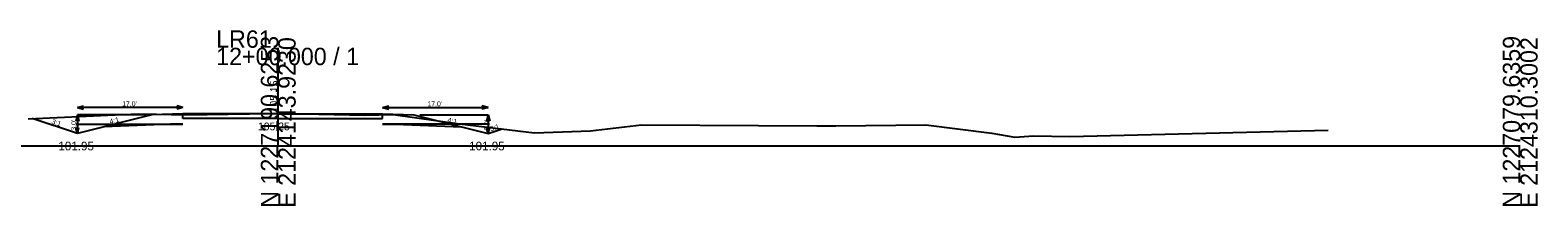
# Model space of a CAD drawing. Extents: x -26 to 1403, y -10 to 9574.
# Drawn here: x 1160 to 1402.8, y 1990.3 to 2018.6 of the extents above; entities that cross this region are included whole.
import ezdxf

# ---------------------------------------------------------------- set-up
doc = ezdxf.new("R2010")
doc.units = 0
for name, color, linetype in [('XS_CELL', 7, 'Continuous'), ('XS_P_FINISHED_GRADE', 7, 'Continuous'), ('XS_P_FINISHED_GRADE_ELEV_TX', 7, 'Continuous'), ('XS_P_SUBGRADE_GRANULAR', 7, 'Continuous'), ('XS_P_SUBGRADE_PAVEMENT', 7, 'Continuous'), ('XS_P_TX_CLEARZONE', 7, 'Continuous'), ('XS_P_TX_DCH', 7, 'Continuous'), ('XS_P_TX_FS_BS', 7, 'Continuous'), ('XS_X_GROUND', 7, 'Continuous'), ('XS_X_GROUND_TX', 7, 'Continuous')]:
    doc.layers.add(name, color=color, linetype=linetype)

msp = doc.modelspace()

# ---------------------------------------------------------------- linework, layer by layer
at = {"layer": 'XS_CELL'}
for p, q in [((1200, 2000), (1200, 2015.78)), ((1000, 2000), (1200, 2000)), ((1200, 2000), (1400, 2000))]:
    msp.add_line(p, q, dxfattribs=at)
at = {"layer": 'XS_P_FINISHED_GRADE'}
for p, q in [((1167.66, 2001.95), (1160.37, 2004.38)), ((1179.66, 2004.95), (1167.66, 2001.95)), ((1184.66, 2005.15), (1179.66, 2004.95)), ((1200, 2005.15), (1184.66, 2005.15)), ((1200, 2005.15), (1216.81, 2005.15)), ((1216.81, 2005.15), (1221.81, 2004.95)), ((1221.81, 2004.95), (1233.81, 2001.95)), ((1233.81, 2001.95), (1236.04, 2002.7))]:
    msp.add_line(p, q, dxfattribs=at)
at = {"layer": 'XS_P_SUBGRADE_GRANULAR'}
for p, q in [((1167.46, 2003.45), (1184.66, 2003.45)), ((1182.66, 2003.45), (1171.94, 2003.03)), ((1184.66, 2003.45), (1182.66, 2003.45)), ((1234.01, 2003.45), (1216.81, 2003.45)), ((1216.81, 2003.45), (1218.81, 2003.45)), ((1218.81, 2003.45), (1229.53, 2003.03))]:
    msp.add_line(p, q, dxfattribs=at)
at = {"layer": 'XS_P_SUBGRADE_PAVEMENT'}
for p, q in [((1184.66, 2004.4), (1184.66, 2005.15)), ((1200, 2004.4), (1184.66, 2004.4)), ((1200, 2004.4), (1216.81, 2004.4)), ((1216.81, 2004.4), (1216.81, 2005.15))]:
    msp.add_line(p, q, dxfattribs=at)
at = {"layer": 'XS_P_TX_CLEARZONE'}
for p, q in [((1167.66, 2006.15), (1168.66, 2006.4)), ((1167.66, 2006.15), (1168.66, 2005.9)), ((1184.66, 2006.15), (1167.66, 2006.15)), ((1184.66, 2006.15), (1183.66, 2006.4)), ((1184.66, 2006.15), (1183.66, 2005.9)), ((1216.81, 2006.15), (1217.81, 2006.4)), ((1216.81, 2006.15), (1217.81, 2005.9)), ((1216.81, 2006.15), (1233.81, 2006.15)), ((1233.81, 2006.15), (1232.81, 2006.4)), ((1233.81, 2006.15), (1232.81, 2005.9)), ((1167.66, 2004.95), (1167.41, 2003.95)), ((1167.66, 2004.95), (1167.91, 2003.95)), ((1167.66, 2004.95), (1167.66, 2001.95)), ((1178.66, 2004.95), (1167.66, 2004.95)), ((1222.81, 2004.95), (1233.81, 2004.95)), ((1233.81, 2004.95), (1233.56, 2003.95)), ((1233.81, 2004.95), (1233.81, 2001.95)), ((1233.81, 2004.95), (1234.06, 2003.95)), ((1167.66, 2001.95), (1167.41, 2002.95)), ((1167.66, 2001.95), (1167.91, 2002.95)), ((1233.81, 2001.95), (1233.56, 2002.95)), ((1233.81, 2001.95), (1234.06, 2002.95))]:
    msp.add_line(p, q, dxfattribs=at)
at = {"layer": 'XS_X_GROUND'}
for p, q in [((1159.72, 2004.35), (1173.76, 2004.95)), ((1173.76, 2004.95), (1177.52, 2005.12)), ((1177.52, 2005.12), (1180.37, 2005.06)), ((1180.37, 2005.06), (1185.14, 2004.96)), ((1185.14, 2004.96), (1195.37, 2005.16)), ((1195.37, 2005.16), (1199.82, 2005.26)), ((1199.82, 2005.26), (1206.54, 2005.1)), ((1206.54, 2005.1), (1213.95, 2004.91)), ((1213.95, 2004.91), (1218.51, 2005.01)), ((1218.51, 2005.01), (1229.2, 2003.51)), ((1229.2, 2003.51), (1241.29, 2002.08)), ((1250.26, 2002.41), (1258.51, 2003.36)), ((1258.51, 2003.36), (1286.75, 2003.19)), ((1286.75, 2003.19), (1288.25, 2003.21)), ((1288.25, 2003.21), (1289.8, 2003.18)), ((1289.8, 2003.18), (1304.27, 2003.37)), ((1304.27, 2003.37), (1314.92, 2002.02)), ((1241.29, 2002.08), (1250.26, 2002.41)), ((1314.92, 2002.02), (1318.64, 2001.37)), ((1318.64, 2001.37), (1321.61, 2001.6)), ((1321.61, 2001.6), (1327.48, 2001.5)), ((1327.48, 2001.5), (1369.05, 2002.5))]:
    msp.add_line(p, q, dxfattribs=at)

# ---------------------------------------------------------------- texts
at = {"layer": 'XS_CELL'}
for s, p in [('LR61', (1190, 2015.78)), ('12+00.000 / 1', (1190, 2012.98))]:
    msp.add_text(s, height=2.8, dxfattribs=at).set_placement(p)
for s, p in [('N 1227190.6253', (1200, 1990)), ('E 2124143.9230', (1202.8, 1990)), ('N 1227079.6359', (1400, 1990)), ('E 2124310.3002', (1402.8, 1990))]:
    msp.add_text(s, height=2.8, rotation=90, dxfattribs=at).set_placement(p)
at = {"layer": 'XS_P_FINISHED_GRADE_ELEV_TX'}
msp.add_text('105.15', height=1.25, rotation=90, dxfattribs=at).set_placement((1199.92, 2005.38))
at = {"layer": 'XS_P_TX_CLEARZONE'}
for p in [(1174.87, 2006.35), (1224.03, 2006.35)]:
    msp.add_text("17.0'", height=0.8, dxfattribs=at).set_placement(p)
for p in [(1167.46, 2002.43), (1234.01, 2002.43)]:
    msp.add_text("3.0'", height=0.8, rotation=90, dxfattribs=at).set_placement(p)
at = {"layer": 'XS_P_TX_DCH'}
for p in [(1164.59, 1999.25), (1230.74, 1999.25)]:
    msp.add_text('101.95', height=1.4, dxfattribs=at).set_placement(p)
at = {"layer": 'XS_P_TX_FS_BS'}
for s, rotation, p in [('3:1', 341.5675, (1163.43, 2003.57)), ('4:1', 14.0343, (1172.95, 2003.48)), ('4:1', 345.9663, (1227.2, 2003.81)), ('3:1', 18.4317, (1234.22, 2002.3))]:
    msp.add_text(s, height=0.8, rotation=rotation, dxfattribs=at).set_placement(p)
at = {"layer": 'XS_X_GROUND_TX'}
msp.add_text('105.25', height=1.25, rotation=360, dxfattribs=at).set_placement((1196.74, 2002.48))

doc.saveas('drawing.dxf')
